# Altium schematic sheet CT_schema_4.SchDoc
size 368 x 245 mm
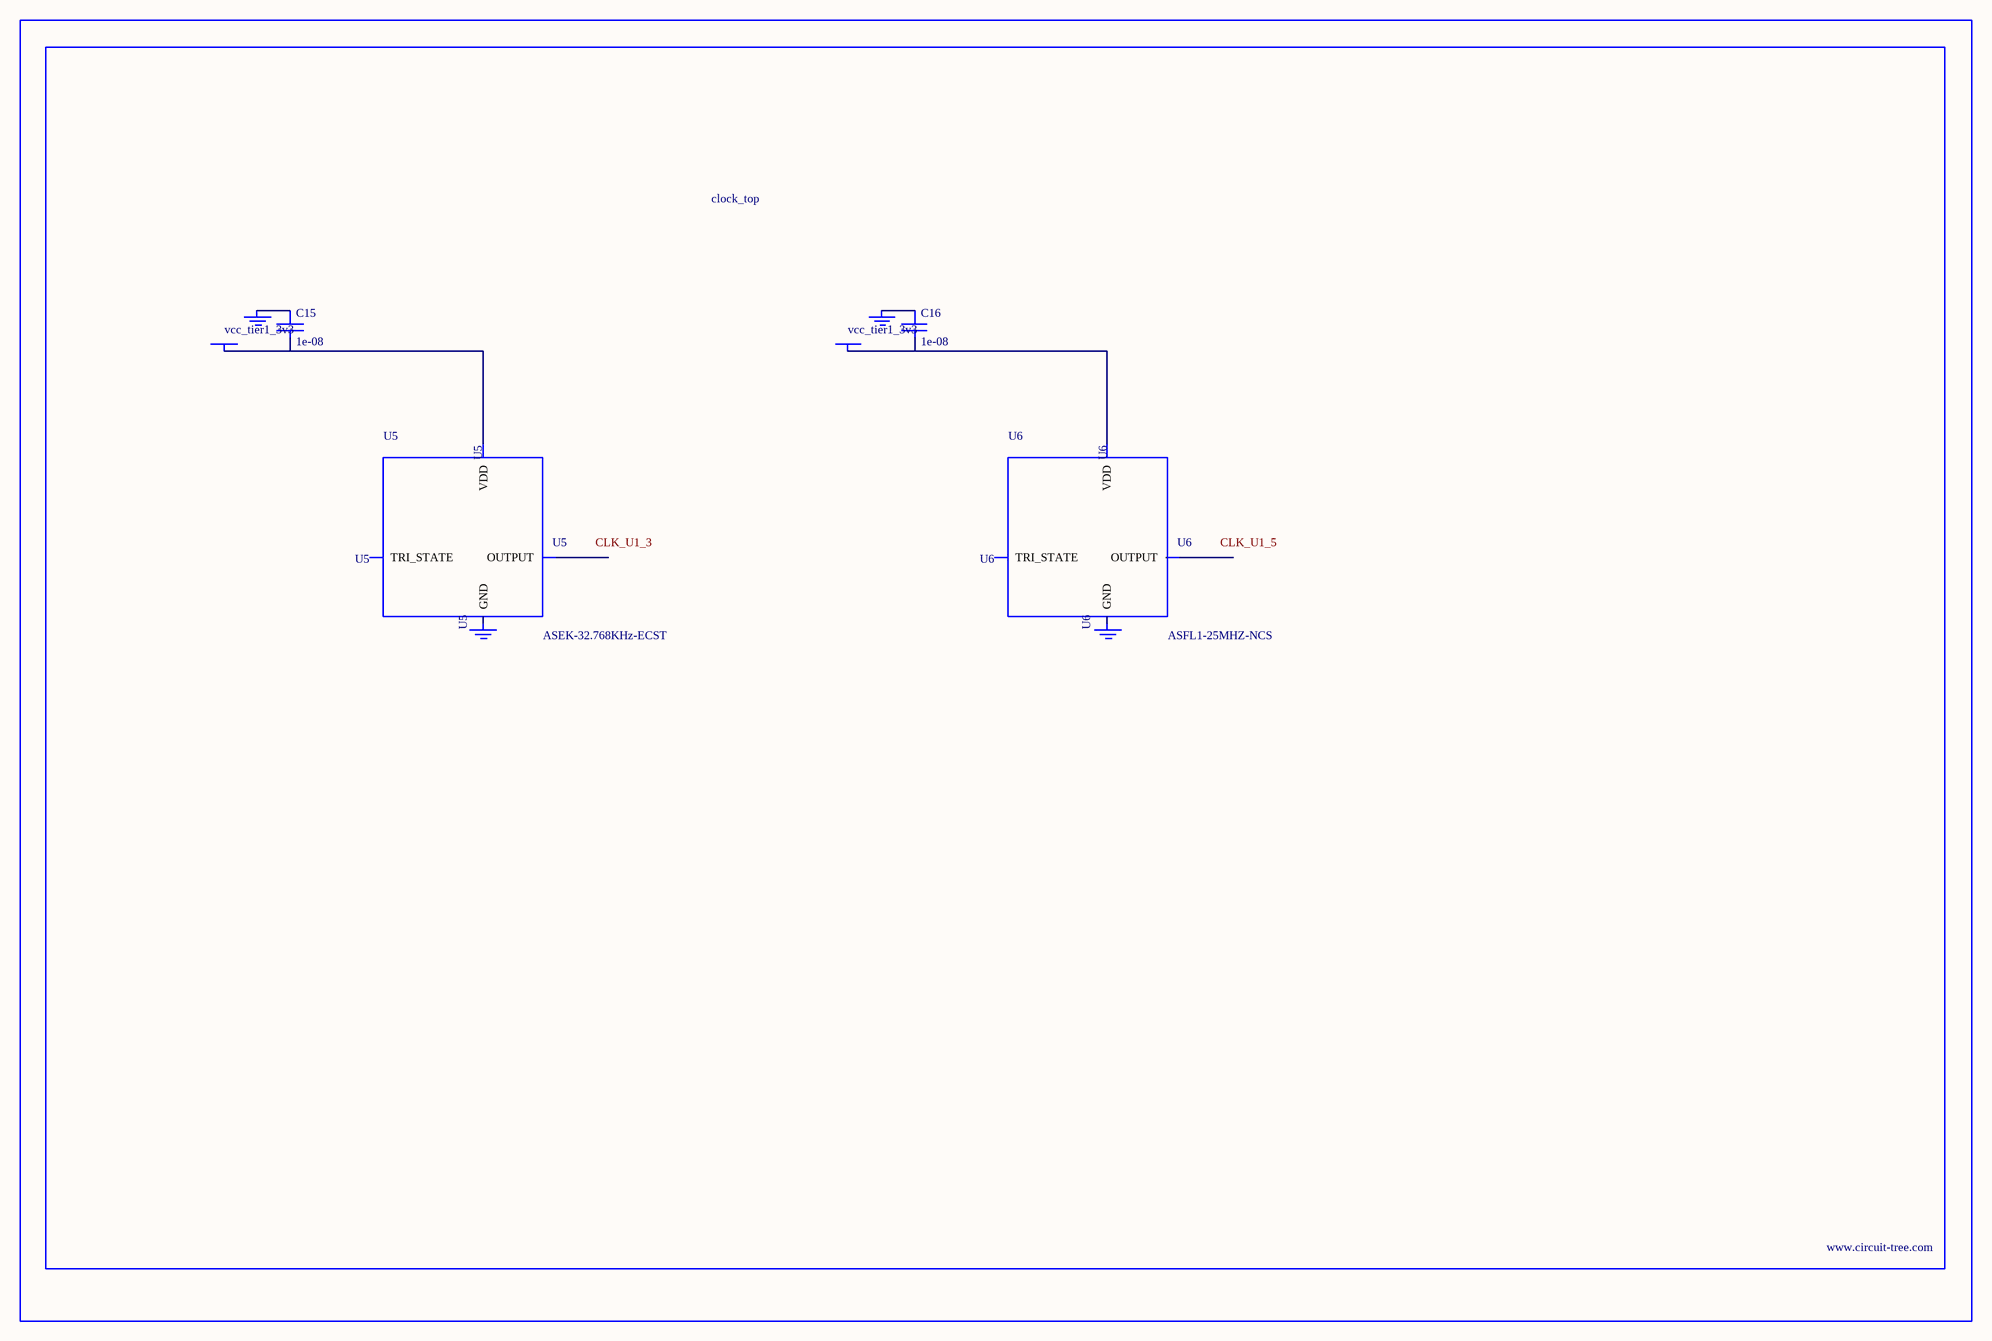
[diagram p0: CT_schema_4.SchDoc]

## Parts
BORDER3  (no value)
C15  1e-08  [C0402]
C16  1e-08  [C0402]
GND_INSTANCE_3_0  (no value)
GND_INSTANCE_3_1  (no value)
GND_INSTANCE_3_2  (no value)
GND_INSTANCE_3_3  (no value)
POWER_INSTANCE_3_0  vcc_tier1_3v3
POWER_INSTANCE_3_1  vcc_tier1_3v3
U5  ASEK-32.768KHz-ECST  [ASEK]
U6  ASFL1-25MHZ-NCS  [ASFL1]

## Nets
NetC15_1: C15.1 GND_INSTANCE_3_0.0(GND)
NetC15_2: C15.2 POWER_INSTANCE_3_0.0(PWR) U5.4(VDD)
NetC16_1: C16.1 GND_INSTANCE_3_2.0(GND)
NetC16_2: C16.2 POWER_INSTANCE_3_1.0(PWR) U6.4(VDD)

Not connected (* = marked no-connect by the designer): GND_INSTANCE_3_1 0(GND); GND_INSTANCE_3_3 0(GND); U5 1(TRI_STATE) 2(GND) 3(OUTPUT); U6 1(TRI_STATE) 2(GND) 3(OUTPUT)

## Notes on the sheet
- Labels drawn without touching a wire or pin: CLK_U1_3, CLK_U1_5

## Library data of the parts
BORDER3 = BORDER_PAGE3
C15 C16 = C0402C103K3RAC
GND_INSTANCE_3_0-GND_INSTANCE_3_3 = GND
POWER_INSTANCE_3_0 POWER_INSTANCE_3_1 = PWR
